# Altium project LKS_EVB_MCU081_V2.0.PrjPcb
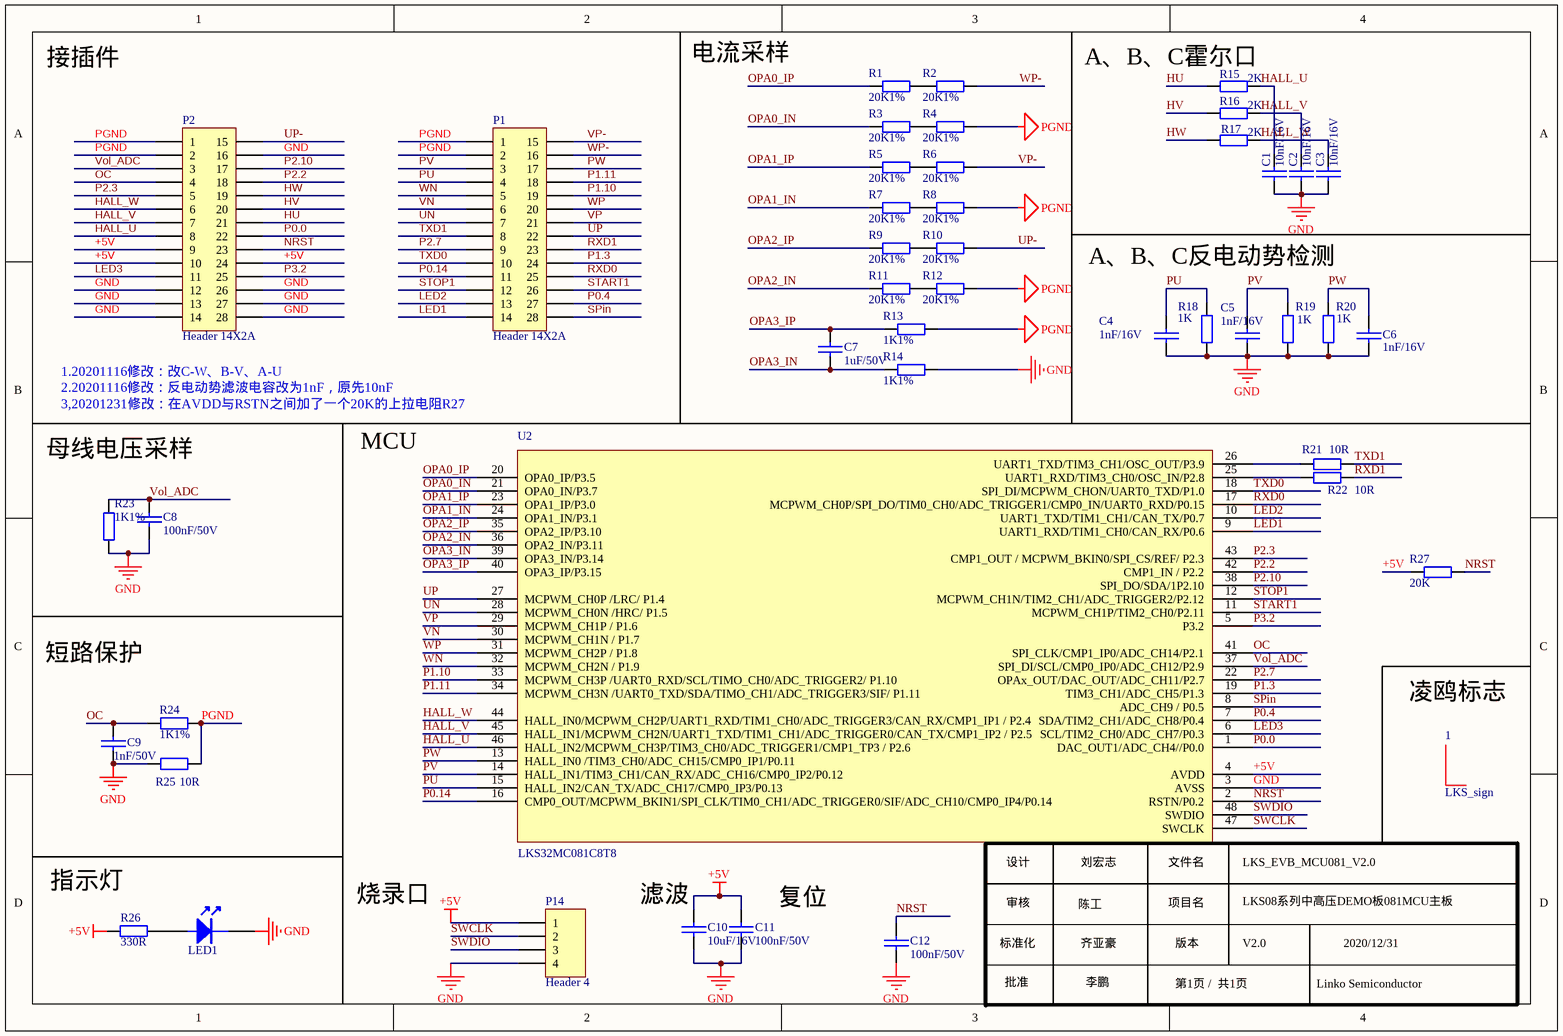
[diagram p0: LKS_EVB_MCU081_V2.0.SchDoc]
1 sheet, 45 parts. Net scope: global (net labels, ports and power ports of the same name join across sheets).
Board file: LKS_EVB_MCU081_V2.0.PcbDoc

## Sheet LKS_EVB_MCU081_V2.0.SchDoc
size A4; SheetNumber: 1; SheetTotal: 1

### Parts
1  LKS_sign  [LKS_LOGO2]
C1  10nF/16V  [0603C]
C2  10nF/16V  [0603C]
C3  10nF/16V  [0603C]
C4  1nF/16V  [0603C]
C5  1nF/16V  [0603C]
C6  1nF/16V  [0603C]
C7  1uF/50V  [0603C]
C8  100nF/50V  [0603C]
C9  1nF/50V  [0603C]
C10  10uF/16V  [0603C]
C11  100nF/50V  [0603C]
C12  100nF/50V  [0603C]
LED1  LED  [LED 0603R]  (value not drawn)
P1  Header 14X2A  [HDR2X14_CEN]
P2  Header 14X2A  [HDR2X14_CEN]
P14  Header 4  [HDR1X4]
R1  20K1%  [0603R]
R2  20K1%  [0603R]
R3  20K1%  [0603R]
R4  20K1%  [0603R]
R5  20K1%  [0603R]
R6  20K1%  [0603R]
R7  20K1%  [0603R]
R8  20K1%  [0603R]
R9  20K1%  [0603R]
R10  20K1%  [0603R]
R11  20K1%  [0603R]
R12  20K1%  [0603R]
R13  1K1%  [0603R]
R14  1K1%  [0603R]
R15  2K  [0603R]
R16  2K  [0603R]
R17  2K  [0603R]
R18  1K  [0603R]
R19  1K  [0603R]
R20  1K  [0603R]
R21  10R  [0603R]
R22  10R  [0603R]
R23  1K1%  [0603R]
R24  1K1%  [0603R]
R25  10R  [0603R]
R26  330R  [0603R]
R27  20K  [0603R]
U2  LKS32MC081C8T8  [LINKO-081]

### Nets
+5V: C10.2 C11.2 P2.9 P2.10 P2.24 P14.1 R26.1 R27.2 U2.4(AVDD)
GND: C1.2 C2.2 C3.2 C4.2 C5.2 C6.2 C8.1 C9.1 C10.1 C11.1 C12.2 LED1.2(K) P2.12 P2.13 P2.14 P2.16 P2.26 P2.27 P2.28 P14.4 R14.1 R18.2 R19.2 R20.2 R23.1 R25.2 U2.3(AVSS)
PGND: P1.1 P1.2 P2.1 P2.2 R4.1 R8.1 R12.1 R13.1 R24.2 R25.1
HALL_U: C1.1 P2.8 R15.2 U2.46(HALL_IN2/MCPWM_CH3P/TIM3_CH0/ADC_TRIGGER1/CMP1_TP3_/_P2.6)
HALL_V: C2.1 P2.7 R16.2 U2.45(HALL_IN1/MCPWM_CH2N/UART1_TXD/TIM1_CH1/ADC_TRIGGER0/CAN_TX/CMP1_IP2_/_P2.5)
HALL_W: C3.1 P2.6 R17.2 U2.44(HALL_IN0/MCPWM_CH2P/UART1_RXD/TIM1_CH0/ADC_TRIGGER3/CAN_RX/CMP1_IP1_/_P2.4)
HU: P2.21 R15.1
HV: P2.20 R16.1
HW: P2.19 R17.1
LED1: P1.14 U2.9(UART1_RXD/TIM1_CH0/CAN_RX/P0.6)
LED2: P1.13 U2.10(UART1_TXD/TIM1_CH1/CAN_TX/P0.7)
LED3: P2.11 U2.6(SCL/TIM2_CH0/ADC_CH7/P0.3)
NRST: C12.1 P2.23 R27.1 U2.2(RSTN/P0.2)
OC: C9.2 P2.4 R24.1 U2.41(SPI_CLK/CMP1_IP0/ADC_CH14/P2.1)
OPA0_IN: R3.2 U2.21(OPA0_IN/P3.7)
OPA0_IP: R1.2 U2.20(OPA0_IP/P3.5)
OPA1_IN: R7.2 U2.24(OPA1_IN/P3.1)
OPA1_IP: R5.2 U2.23(OPA1_IP/P3.0)
OPA2_IN: R11.2 U2.36(OPA2_IN/P3.11)
OPA2_IP: R9.2 U2.35(OPA2_IP/P3.10)
OPA3_IN: C7.2 R14.2 U2.39(OPA3_IN/P3.14)
OPA3_IP: C7.1 R13.2 U2.40(OPA3_IP/P3.15)
P0.0: P2.22 U2.1(DAC_OUT1/ADC_CH4//P0.0)
P0.4: P1.27 U2.7(SDA/TIM2_CH1/ADC_CH8/P0.4)
P0.14: P1.11 U2.16(CMP0_OUT/MCPWM_BKIN1/SPI_CLK/TIM0_CH1/ADC_TRIGGER0/SIF/ADC_CH10/CMP0_IP4/P0.14)
P1.3: P1.24 U2.19(TIM3_CH1/ADC_CH5/P1.3)
P1.10: P1.19 U2.33(MCPWM_CH3P_/UART0_RXD/SCL/TIMO_CH0/ADC_TRIGGER2/_P1.10)
P1.11: P1.18 U2.34(MCPWM_CH3N_/UART0_TXD/SDA/TIMO_CH1/ADC_TRIGGER3/SIF/_P1.11)
P2.2: P2.18 U2.42(CMP1_IN_/_P2.2)
P2.3: P2.5 U2.43(CMP1_OUT_/_MCPWM_BKIN0/SPI_CS/REF/_P2.3)
P2.7: P1.9 U2.22(OPAx_OUT/DAC_OUT/ADC_CH11/P2.7)
P2.10: P2.17 U2.38(SPI_DO/SDA/1P2.10)
P3.2: P2.25 U2.5(P3.2)
PU: C4.1 P1.4 R18.1 U2.15(HALL_IN2/CAN_TX/ADC_CH17/CMP0_IP3/P0.13)
PV: C5.1 P1.3 R19.1 U2.14(HALL_IN1/TIM3_CH1/CAN_RX/ADC_CH16/CMP0_IP2/P0.12)
PW: C6.1 P1.17 R20.1 U2.13(HALL_IN0_/TIM3_CH0/ADC_CH15/CMP0_IP1/P0.11)
RXD0: P1.25 U2.17(MCPWM_CH0P/SPI_DO/TIM0_CH0/ADC_TRIGGER1/CMP0_IN/UART0_RXD/P0.15)
RXD1: P1.23 R22.2
SPin: P1.28 U2.8(ADC_CH9_/_P0.5)
START1: P1.26 U2.11(MCPWM_CH1P/TIM2_CH0/P2.11)
STOP1: P1.12 U2.12(MCPWM_CH1N/TIM2_CH1/ADC_TRIGGER2/P2.12)
SWCLK: P14.2 U2.47(SWCLK)
SWDIO: P14.3 U2.48(SWDIO)
TXD0: P1.10 U2.18(SPI_DI/MCPWM_CHON/UART0_TXD/P1.0)
TXD1: P1.8 R21.1
UN: P1.7 U2.28(MCPWM_CH0N_/HRC/_P1.5)
UP: P1.22 U2.27(MCPWM_CH0P_/LRC/_P1.4)
UP-: P2.15 R10.1
VN: P1.6 U2.30(MCPWM_CH1N_/_P1.7)
Vol_ADC: C8.2 P2.3 R23.2 U2.37(SPI_DI/SCL/CMP0_IP0/ADC_CH12/P2.9)
VP: P1.21 U2.29(MCPWM_CH1P_/_P1.6)
VP-: P1.15 R6.1
WN: P1.5 U2.32(MCPWM_CH2N_/_P1.9)
WP: P1.20 U2.31(MCPWM_CH2P_/_P1.8)
WP-: P1.16 R2.1
NetLED1_1: LED1.1(A) R26.2
NetR1_1: R1.1 R2.2
NetR3_1: R3.1 R4.2
NetR5_1: R5.1 R6.2
NetR7_1: R7.1 R8.2
NetR9_1: R9.1 R10.2
NetR11_1: R11.1 R12.2
NetR21_2: R21.2 U2.26(UART1_TXD/TIM3_CH1/OSC_OUT/P3.9)
NetR22_1: R22.1 U2.25(UART1_RXD/TIM3_CH0/OSC_IN/P2.8)

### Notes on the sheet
- 接插件
- 电流采样
- A、B、C霍尔口
- A、B、C反电动势检测
- (near P2) 1.20201116修改：改C-W、B-V、A-U
- 2.20201116修改：反电动势滤波电容改为1nF，原先10nF
- 3,20201231修改：在AVDD与RSTN之间加了一个20K的上拉电阻R27
- MCU
- 母线电压采样
- 短路保护
- (near 1) 凌鸥标志
- (near R26) 指示灯
- 烧录口
- (near C10) 滤波
- 复位
- (near U2) 设计
- 审核
- 陈工
- (near U2) 刘宏志
- (near U2) 文件名
- 项目名
- (near U2) LKS_EVB_MCU081_V2.0
- LKS08系列中高压DEMO板081MCU主板
- 标准化
- 批准
- 齐亚豪
- 李鹏
- 版本
- 第1页 /  共1页
- V2.0
- Linko Semiconductor
- 2020/12/31

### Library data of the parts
C1-C6 = CAP: Capacitor
C7-C12 = C: Capacitor
LED1 = LED: LED_Light
P1 P2 = Header 14X2A: Header, 14-Pin, Dual row
P14 = Header 4: Header, 4-Pin
R1-R25 R27 = Res: Resistor; Value: K
R26 = Res: Resistor; Value: 330
U2 = LKS081C8T8: 芯片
